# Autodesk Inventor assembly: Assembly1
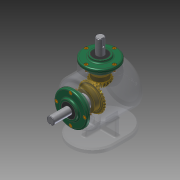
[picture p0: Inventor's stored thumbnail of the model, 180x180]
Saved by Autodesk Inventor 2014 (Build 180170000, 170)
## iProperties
Created: 2016-04
Part Number: Assembly1
Document SubType Name: Assembly
Designer: user
Author: user
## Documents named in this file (14)
- C:\Users\user\Desktop\460408V1013\Assembly1.iam
- C:\Users\user\Desktop\460408V1013\본체.ipt
- C:\Users\user\Desktop\460408V1013\커버.ipt
- C:\Users\user\Desktop\460408V1013\M4.ipt
- C:\Users\user\Desktop\460408V1013\오일실 17 32 8.ipt
- C:\Users\user\Desktop\460408V1013\메인 축.ipt
- 메인 축.ipt
- C:\Users\user\Desktop\460408V1013\키 5x5.ipt
- C:\Users\user\Desktop\460408V1013\메인 베벨기어.ipt
- C:\Users\user\Desktop\460408V1013\베어링 6203.ipt
- C:\Users\user\Desktop\460408V1013\서브 축.ipt
- 서브 축.ipt
- C:\Users\user\Desktop\460408V1013\키 4x4.ipt
- C:\Users\user\Desktop\460408V1013\서브 베벨기어.ipt
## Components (8 placed, 1 different names)
1. M4:3 — Insert:4
2. M4:4
3. M4:5
4. M4:6
5. M4:2 — Insert:3
6. M4:7
7. M4:8
8. M4:9
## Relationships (2: Insert 2)
- Insert:3: M4:2
- Insert:4: M4:3
